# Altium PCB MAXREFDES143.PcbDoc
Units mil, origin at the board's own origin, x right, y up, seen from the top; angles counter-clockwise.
Board outline 3455 x 3500 mil, 2 copper layers (Top Layer, Bottom Layer); 65 components, 50 nets, 221 pads, 48 vias.
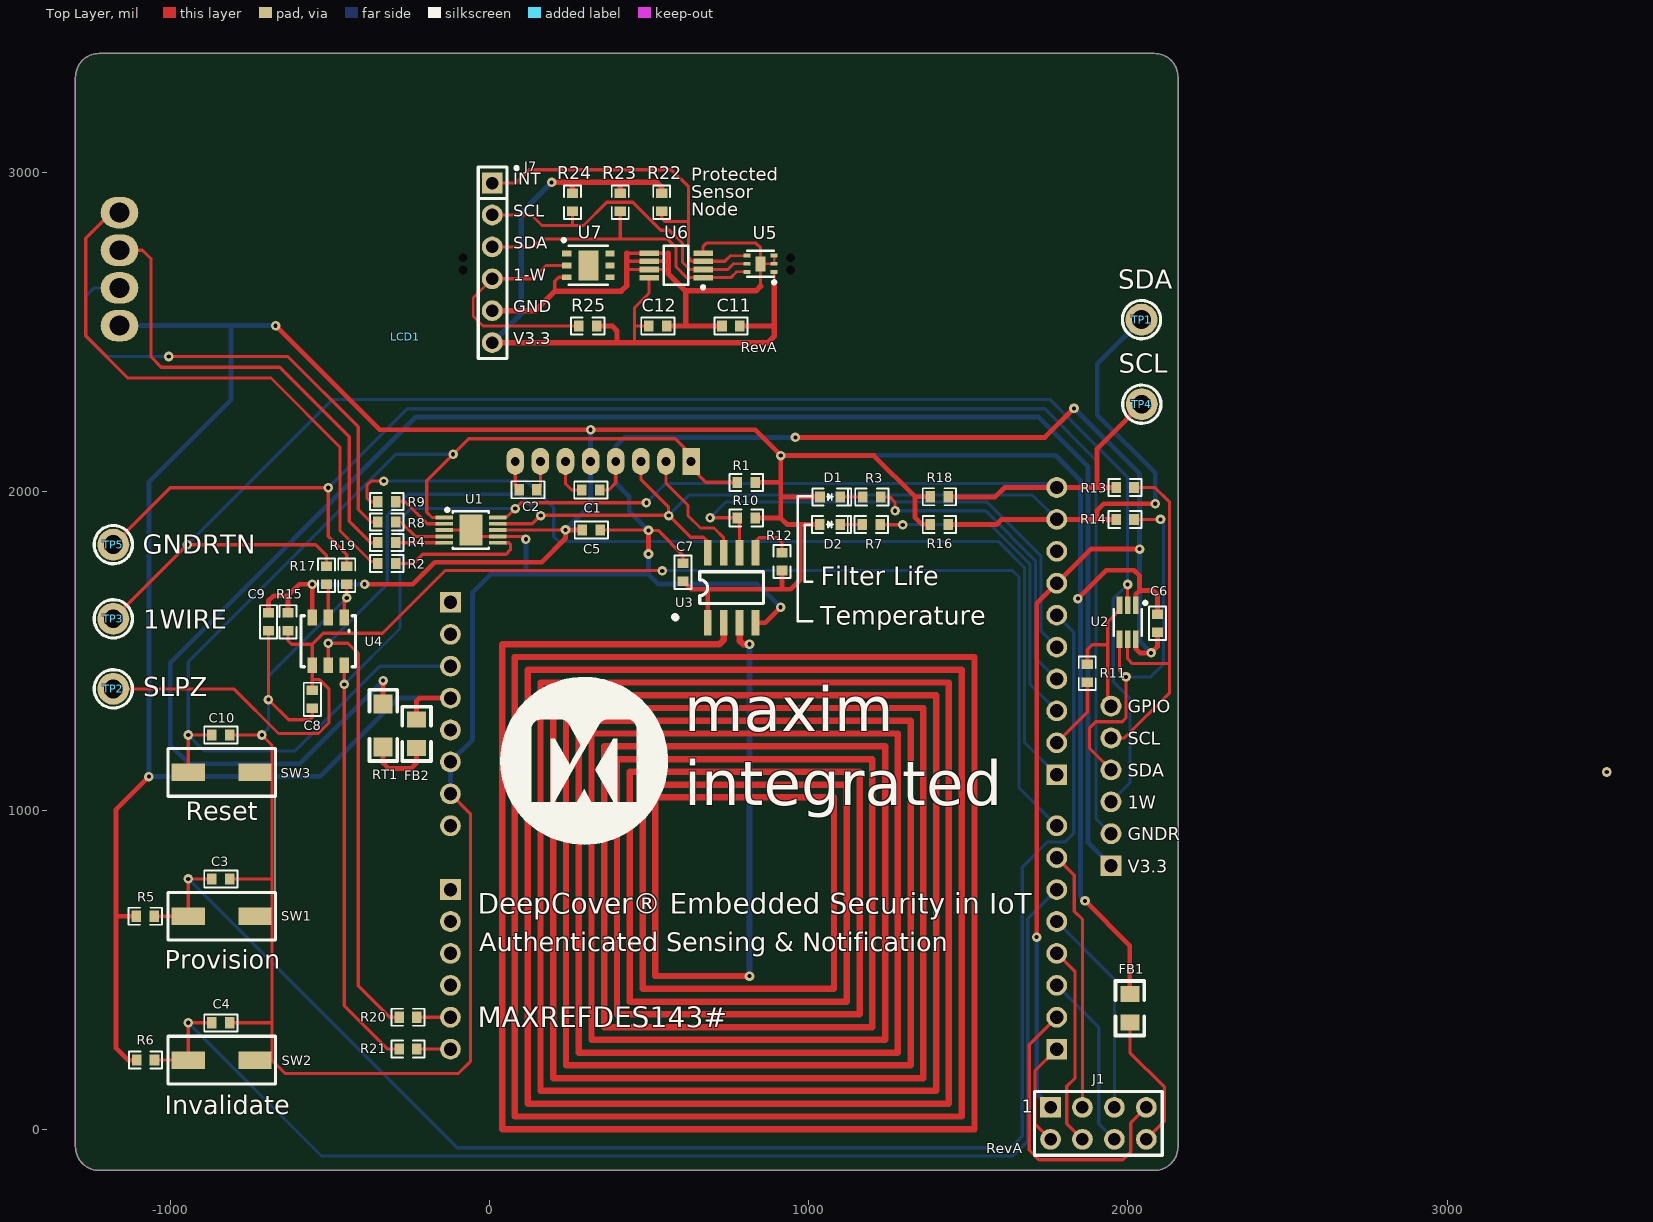
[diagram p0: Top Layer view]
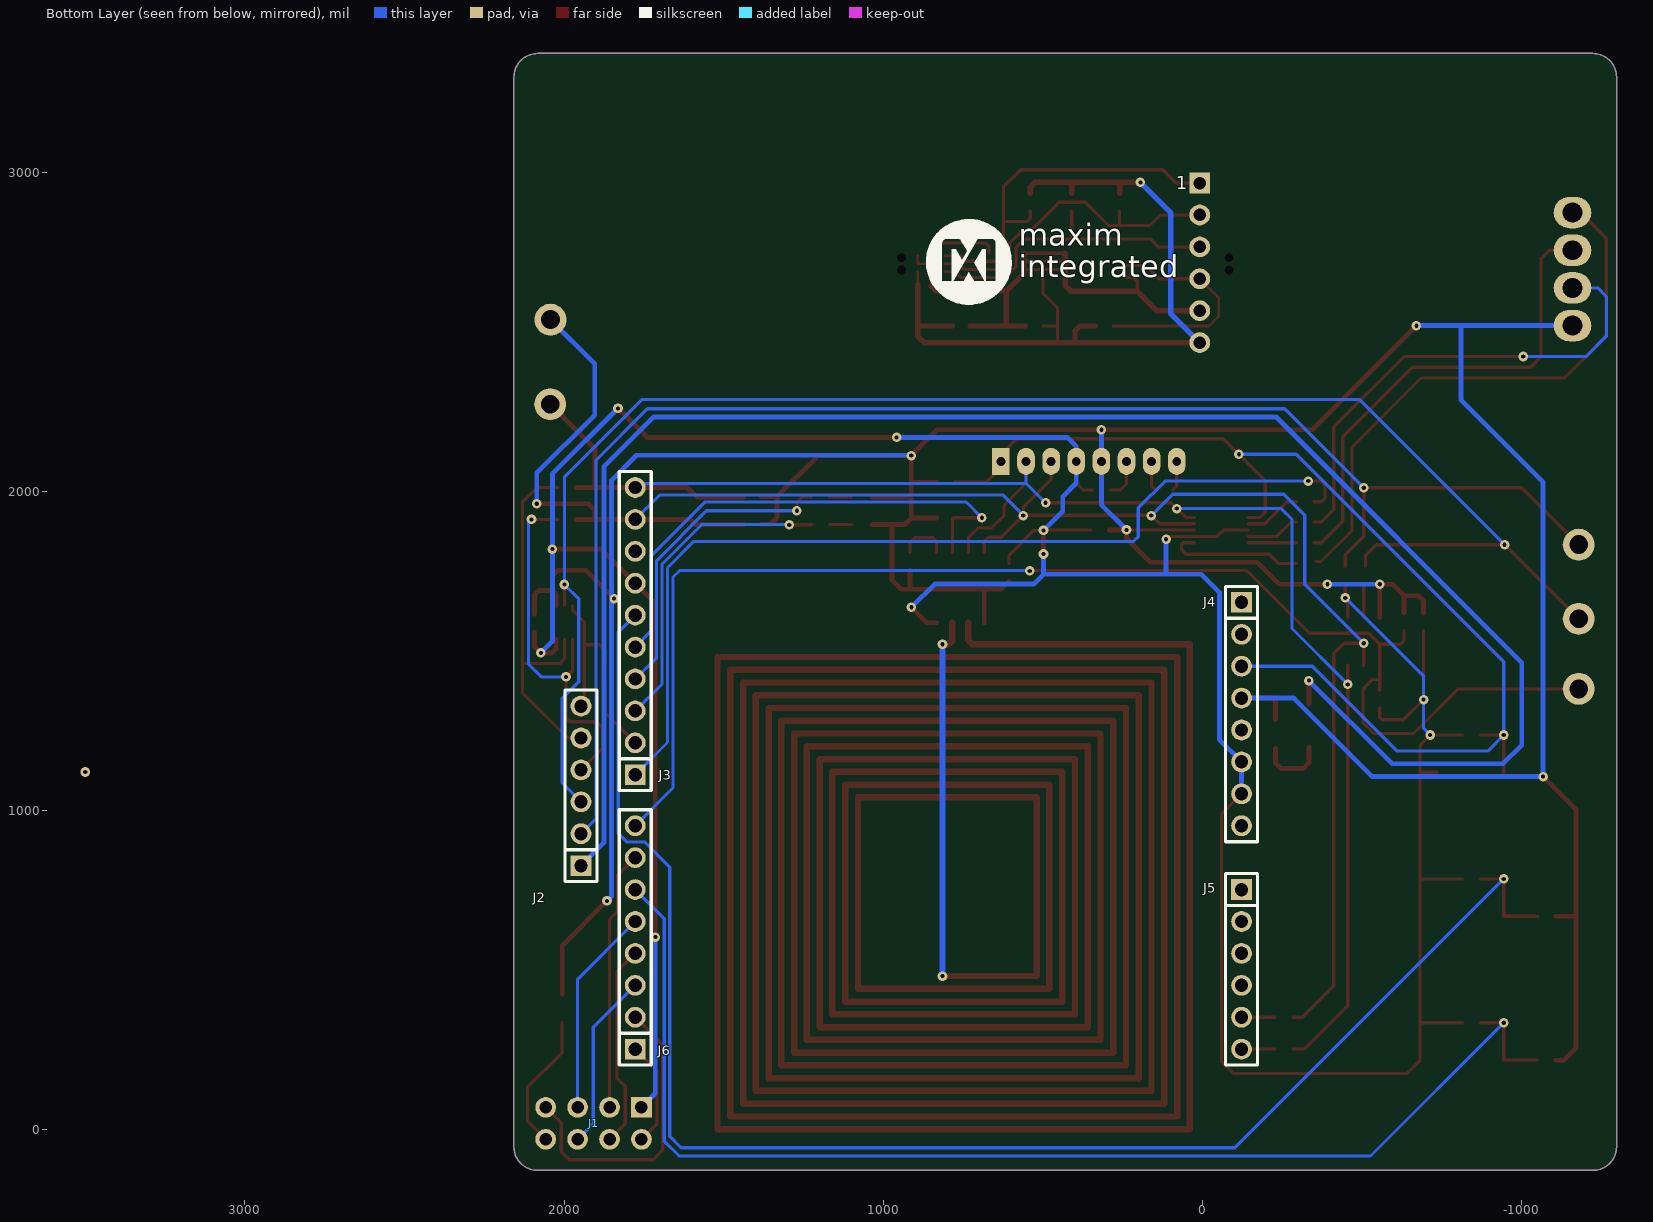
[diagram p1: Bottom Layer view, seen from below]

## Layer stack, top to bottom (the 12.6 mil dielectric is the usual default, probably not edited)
Top Layer: signal copper 1.4
Dielectric: core 12.6, FR-4, Dk 4.8
Bottom Layer: signal copper 1.4

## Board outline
-1298,-53.07 ccw(c-1224.07,-53.07) -1224.07,-127 2083.07,-127 ccw(c2083.07,-53.07) 2157,-53.07 2157,3299.07 ccw(c2083.07,3299.07) 2083.07,3373 -1224.07,3373 ccw(c-1224.07,3299.07) -1298,3299.07

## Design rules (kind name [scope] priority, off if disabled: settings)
Clearance "Clearance GND Layer" [(OnLayer('GND Layer'))] p1: gap=8
Clearance "Clearance V3.3 layer" [(OnLayer('V3.3 Layer'))] p2: gap=8
Clearance [All] p3: gap=7
ComponentClearance [All] p1: gap=0 collisioncheckmode=3 verticalgap=0 showdistances=FALSE
HoleSize [All] p1: absolutevalues=TRUE maxlimit=1000 minlimit=1 maxpercent=80.000 minpercent=20.000
MinimumSolderMaskSliver [All] p1: minsoldermaskwidth=0
PolygonConnect [All] p1: connectstyle=Relief reliefconductorwidth=10 reliefentries=4 polygonreliefangle="90 Angle"
RoomDefinition ProtectedSensorNode [InComponentClass('ProtectedSensorNode')] p1: confinementstyle=ConfineIn formatcopy=TRUE lockcomponents=FALSE outline -348,2304 1114,2304 1114,3140 -348,3140
RoomDefinition mbedShield [InComponentClass('mbedShield')] p2: confinementstyle=ConfineIn formatcopy=TRUE lockcomponents=FALSE outline -1451,-292 2335,-292 2335,3550 -1451,3550
RoutingVias [All] p1: holewidth=6 width=16 viastyle="Through Hole" minholewidth=6 minwidth=12 maxholewidth=17 maxwidth=35
SilkToSilkClearance [All] p1: silktosilkclearance=0
SilkscreenOverComponentPads [All] p1: minsilkscreentomaskgap=4
SolderMaskExpansion [All] p1: expansion=4
Width [All] p1: maxlimit=1111 minlimit=1 preferedwidth=25
23 further rules are at their usual default settings.

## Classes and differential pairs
component class ProtectedSensorNode: C11 C12 J7 R22 R23 R24 R25 U5 U6 U7
component class mbedShield: C1 C2 C3 C4 C5 C6 C7 C8 C9 C10 D1 D2 FB1 FB2 J1 J2 J3 J4 J5 J6 LCD1 R1 R2 R3 R4 R5 R6 R7 R8 R9 R10 R11 R12 R13 R14 R15 R16 R17 R18 R19 R20 R21 RT1 SW1 SW2 SW3 TP1 TP2 TP3 TP4 TP5 U1 U2 U3 U4

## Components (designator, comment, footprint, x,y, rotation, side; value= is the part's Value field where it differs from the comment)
C1 "1uF" CAP0603-3D 289,2005 r0 top
C2 "1uF" CAP0603-3D 148,2006 r180 top
C3 "0.1uF" CAP0603-3D -870.5,786.5 r0 top
C4 "0.1uF" CAP0603-3D -870.5,335.5 r0 top
C5 "0.1uF" CAP0603-3D 290.5,1880 r0 top
C6 "0.1uF" CAP0603-3D 2092.5,1615.5 r270 top
C7 "0.1uF" CAP0603-3D 605.5,1719.5 r90 top
C8 "0.1uF" CAP0603-3D -556,1321 r90 top
C9 "0.1uF" CAP0603-3D -693.5,1564 r90 top
C10 "0.1uF" CAP0603-3D -870.5,1237.5 r0 top
C11 "0.1uF" CAP0603-3D 784,2519 r180 top
C12 "0.1uF" CAP0603-3D 499,2519 r0 top
D1 "RED" 0603LED-3DRED 1099,1983.5 r180 top
D2 "RED" 0603LED-3DRED 1098,1897 r180 top
FB1 "BLM21PG221SN1D" 0805FB-3D 2006,426 r270 top
FB2 "BLM21PG221SN1D" 0805FB-3D -229,1196 r90 top
J1 "ESP8266 Socket" DIH4X2 1757.5,70.5 r270 bottom
J2 "CON6" SIP6 1947,828 r90 bottom locked
J3 "CON10" SIP10-FEM-3D 1777,1113 r90 bottom locked
J4 "CON8" SIP8-FEM-3D -123,1653 r270 bottom locked
J5 "CON6" SIP6-FEM-3D -123,753 r270 bottom locked
J6 "CON8" SIP8-FEM-3D 1777,253 r90 bottom locked
J7 "CON6" SIP6-HEADER-RA-3D 8,2967 r270 top
LCD1 "NHD-C0220BiZ-FS(RGB)-FBW-3VM" "NHD RGB LCD 1" 80,2095 r0 top locked
R1 "DNI" 0603-3D 776,2029 r0 top
R2 "10" 0603-3D -294.63,1775.13 r180 top
R3 "1.5k" 0603-3D 1225.5,1983.5 r180 top
R4 "60.4" 0603-3D -294.63,1840.13 r180 top
R5 "10k" 0603-3D -1051.5,669.5 r180 top
R6 "10k" 0603-3D -1050.5,218.5 r180 top
R7 "1.5k" 0603-3D 1223.5,1897 r180 top
R8 "60.4" 0603-3D -350.63,1904.63 r0 top
R9 "DNI" 0603-3D -294.5,1968.5 r180 top
R10 "10k" 0603-3D 776,1917 r0 top
R11 "10" 0603-3D 1872.5,1403 r90 top
R12 "DNI" 0603-3D 915.5,1809 r270 top
R13 "10" 0603-3D 1963,2013 r0 top
R14 "10" 0603-3D 1963,1913 r0 top
R15 "10K" 0603-3D -632.5,1564 r90 top
R16 "4.7k" 0603-3D 1437,1897.5 r180 top
R17 "5.11" 0603-3D -511,1766 r270 top
R18 "4.7k" 0603-3D 1437,1984 r180 top
R19 "5.11" 0603-3D -448,1766 r270 top
R20 "DNI" 0603-3D -284,353 r0 top
R21 "DNI" 0603-3D -284,253 r0 top
R22 "DNI" 0603-3D 539,2879 r90 top
R23 "DNI" 0603-3D 409,2879 r90 top
R24 "DNI" 0603-3D 259,2879 r90 top
R25 "DNI" 0603-3D 279,2519 r0 top
RT1 "PTC Fuse MF-NSMF012-2" 1206POLYFUSE-3D -334,1200 r90 top
SW1 "PUSH" RESET11-3D -839.81,669.5 r0 top
SW2 "PUSH" RESET11-3D -839.81,218.5 r0 top
SW3 "PUSH" RESET11-3D -839.81,1120.5 r0 top
TP1 "SDA" TP 2042.5,2539 r90 top
TP2 "SLPZ" TP -1179.5,1382 r0 top
TP3 "1-WIRE" TP -1179.5,1601.5 r90 top
TP4 "SCL" TP 2043.5,2274 r90 top
TP5 "GNDRTN" TP -1179.5,1834 r90 top
U1 "MAX7306AUB+" UMAX10 -59,1879.5 r0 top
U2 "MAX13204E" "TDFN6 2MM .65" 2024.5,1643.5 r270 top
U3 "MAX66242" SO-8-3D 683,1589 r90 top
U4 "DS2465" SOP6 -456,1606 r270 top
U5 "MAX44009EDT+" "TDFN6 .65P 2x2MM" 849,2714 r90 top
U6 "DS7505U+" UMAX8 584,2709 r180 top
U7 "DS28E15Q+U" "TDFN6 3MM .95" 309,2709 r0 top

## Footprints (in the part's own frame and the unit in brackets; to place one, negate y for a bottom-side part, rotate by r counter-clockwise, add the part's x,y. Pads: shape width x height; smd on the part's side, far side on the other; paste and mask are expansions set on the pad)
0603-3D [mil]
  rect 30x35 smd: 1(0,0) 2(56,0)
  silkscreen extent -24,-27 80,27, body extent -3,-17 59,17, height 18
0603LED-3DRED [mil]
  rect 30x35 smd: 1(0,0) 2(64,0)
  silkscreen extent -34,-27 88,27, body extent 0,-16 64,15, height 24
0805FB-3D [mil]
  rect 50x60 smd: 1(0,0) 2(90,0)
  silkscreen extent -40,-45 130,45, body extent 6,-24 84,25, height 47
1206POLYFUSE-3D [mil]
  rect 60x60 smd: 1(0,0) 2(134,0)
  silkscreen extent -44,-44 179,43, body extent 4,-33 130,33, height 22
CAP0603-3D [mil]
  rect 30x35 smd: 1(0,0) 2(56,0)
  silkscreen extent -24,-27 80,27, body extent -3,-16 59,16, height 31
DIH4X2 [mil] "dual inline header 4x2 pins"
  rect 65x65 hole 39: 1(0,0)
  round 65 hole 39: 2(100,0) 3(0,-100) 4(100,-100) 5(0,-200) 6(100,-200) 7(0,-300) 8(100,-300)
"NHD RGB LCD 1" [mil] "NHD-C0220BiZ-FSRGB-FBW-3VM"
  rect 55x85 hole 28: 1(551.18,0)
  oval 55x85 hole 28: 2(472.44,0) 3(393.7,0) 4(314.96,0) 5(236.22,0) 6(157.48,0) 7(78.74,0) 8(0,0)
  oval 118.11x98.43 hole 62: A(-1240.16,425.2) B(-1240.16,543.31) G(-1240.16,661.42) R(-1240.16,779.53)
  body extent -1296,-210 1685,1277, height 60
RESET11-3D [mm]
  rect 2.65x1.4 smd: 1(-2.663,0) 2(2.658,0)
  silkscreen extent -4.28,-1.9 4.28,1.9, body extent -3.56,-1.78 3.55,1.78, height 2.54
SIP6 [mil]
  rect 65x65 hole 42: 1(0,0)
  round 65 hole 42: 2(100,0) 3(200,0) 4(300,0) 5(400,0) 6(500,0)
  silkscreen extent -50,-50 550,50
SIP6-FEM-3D [mil]
  rect 65x65 hole 42: 1(0,0)
  round 65 hole 42: 2(100,0) 3(200,0) 4(300,0) 5(400,0) 6(500,0)
  silkscreen extent -50,-50 550,50, body extent -48,-56 549,56, height 336
SIP6-HEADER-RA-3D [mil]
  rect 65x65 hole 39: 1(0,0)
  round 65 hole 39: 2(100,0) 3(200,0) 4(300,0) 5(400,0) 6(500,0)
  silkscreen extent -52,-44 550,81, body extent -50,-354 550,13, height 140
SIP8-FEM-3D [mil]
  rect 65x65 hole 42: 1(0,0)
  round 65 hole 42: 2(100,0) 3(200,0) 4(300,0) 5(400,0) 6(500,0) 7(600,0) 8(700,0)
  silkscreen extent -50,-50 750,50, body extent -48,-56 749,56, height 336
SIP10-FEM-3D [mil]
  rect 65x65 hole 42: 1(0,0)
  round 65 hole 42: 2(100,0) 3(200,0) 4(300,0) 5(400,0) 6(500,0) 7(600,0) 8(700,0) 9(800,0) 10(900,0)
  silkscreen extent -50,-50 950,50, body extent -48,-56 949,56, height 336
SO-8-3D [mil]
  rect 80x24 smd: 1(0,0) 2(0,-50) 3(0,-100) 4(0,-150) 5(220,-150) 6(220,-100) 7(220,-50) 8(220,0)
  silkscreen extent 60,-175 160,25, body extent -8,-172 228,20, height 69
SOP6 [mil]
  rect 50x30 smd: 1(0,0) 2(0,-50) 3(0,-100) 4(150,-100) 5(150,-50) 6(150,0)
  silkscreen extent -5,-135 155,35
"TDFN6 2MM .65" [mm]
  rect 1.4x0.45 smd mask+0.127: 1(0,0) 2(0,-0.65) 3(0,-1.3) 4(2.7,-1.3) 5(2.7,-0.65) 6(2.7,0)
  silkscreen extent -0.33,-1.77 2.4,0.88, body extent 0.33,-1.67 2.37,0.38, height 0.8
"TDFN6 3MM .95" [mm]
  rect 0.75x0.46 smd: 1(-1.725,0.95) 2(-1.725,0) 3(-1.725,-0.95) 4(1.725,-0.95) 5(1.725,0) 6(1.725,0.95)
  rect 1.6x2.39 smd: EP(0,0)
  silkscreen extent -2.08,-1.55 1.55,2.13, body extent -1.55,-1.55 1.55,1.55, height 0.75
"TDFN6 .65P 2x2MM" [mm]
  rect 0.3x0.55 smd: 1(-0.65,-1.075) 2(0,-1.075) 3(0.65,-1.075) 4(0.65,1.075) 5(0,1.075) 6(-0.65,1.075)
  rect 1.2x0.8 smd: EP(0,0)
  silkscreen extent -1.6,-1.2 1.05,1.05, body extent -1.04,-1.04 1.04,1.04, height 0.65
TP [mil]
  round 100 hole 59: 1(0,0)
  silkscreen extent -60,-60 60,60
UMAX8 [mm]
  rect 1.55x0.45 smd: 1(-2.15,0.975) 2(-2.15,0.325) 3(-2.15,-0.325) 4(-2.15,-0.975) 5(2.15,-0.975) 6(2.15,-0.325) 7(2.15,0.325) 8(2.15,0.975)
  silkscreen extent -2.28,-1.55 0.97,1.87, body extent -2.44,-1.51 2.46,1.49, height 1.15
UMAX10 [mm] "TSSOP, 10-Leads, Body 3.0x3.0mm (max), Pitch 0.50mm, IPC Medium Density"
  rect 1.4x0.3 smd: 1(-2.135,1) 2(-2.135,0.5) 3(-2.135,0) 4(-2.135,-0.5) 5(-2.135,-1) 6(2.135,-1) 7(2.135,-0.5) 8(2.135,0) 9(2.135,0.5) 10(2.135,1)
  rect 1.85x2.47 smd: EP(0,0)
  silkscreen extent -2,-1.5 1.42,1.74, body extent -1.5,-1.5 1.5,1.5, height 1.1

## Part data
C1 C2: library part CAP, "CAP CER 1UF 10V 10% X7R 0603"
C3 C4 C5 C6 C7 C8 C9 C10 C11 C12: library part CAP, "CAP CER 0.1UF 16V 10% X7R 0603"
D1 D2: library part LED, "LED RED RECT CLEAR 0603"
FB1 FB2: library part FUSE1, "Ferrite Chip"
J1: library part "JUMPBLOCK 4", "8 Position Header Socket 0.100\" (2.54mm) Through Hole"
J2: "6 Position Header Socket 0.100\" (2.54mm) Through Hole, Right Angle"
J3: "10 Position Header 0.100\" (2.54mm) Through Hole"
J4 J6: "8 Position Header 0.100\" (2.54mm) Through Hole"
J5: "6 Position Header 0.100\" (2.54mm) Through Hole"
J7: "6 Position Header 0.100\" (2.54mm) Through Hole, Right Angle"
LCD1: library part "NHD C0220BiZ-FS(RGB)-FBW-3VM", "LCD DISPLAY RGB LED BKLT 20 X 2"
R1: library part RESISTOR, "RES 10K OHM 1/10W 1% 0603 SMD"
R2 R11 R13 R14: library part RESISTOR, "RES 10 OHM 1/10W 1% 0603 SMD"
R3 R7: library part RESISTOR, "RES SMD 1.5K OHM 1% 1/10W 0603"
R4 R9 R12 R20 R21 R22 R23 R24 R25: library part RESISTOR
R5 R6 R10 R15: library part RESISTOR, "RES SMD 10K OHM 1% 1/10W 0603"
R8: library part RESISTOR, "RES 60.4 OHM 1/10W 1% 0603 SMD"
R16 R18: library part RESISTOR, "RES SMD 4.7K OHM 1% 1/10W 0603"
R17 R19: library part RESISTOR, "RES SMD 5.11 OHM 1% 1/10W 0603"
RT1: library part THERMISTOR, "PTC Fuse 1206"
SW1 SW2 SW3: library part SW-PB, "SWITCH TACTILE SPST-NO 0.05A 32V"
TP1 TP2 TP3 TP4 TP5: library part TP, "Test Point"
U1: library part MAX7306, "SMBus/I²C Interfaced 4-Port, Level-Translating GPIOs and LED Drivers"
U2: library part MAX13204, "4 Channel +/- 30kv ESD Protector"
U3: library part MAX2XXX, "DeepCover Secure Authenticator with ISO 15693, I²C, SHA-256, and 4Kb User EEPROM"
U4: library part DSKCP1, "DeepCover Secure Authenticator with SHA-256 Coprocessor and 1-Wire Master Function"
U5: library part MAX44009, "Ambient Light Sensor with ADC"
U6: library part DS75, "Digital Thermometer and Thermostat"
U7: library part "DS28E15 TDFN", "DeepCover Secure Authenticator with 1-Wire SHA-256 and 512-Bit User EEPROM"

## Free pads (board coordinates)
  round 0 hole 28 unplated: ""(-84,2694) ""(-84,2733) ""(943,2694) ""(943,2733) ""(3498.5,961)
  round 0 hole 28: ""(3497,801)
  round 0 hole 59: ""(3497.5,488)
  round 0 hole 39: ""(3498,648)
  round 0 hole 62: ""(3500,333)

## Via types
v1: diameter 30, hole 13, Top Layer to Bottom Layer, tented both sides, 48 vias

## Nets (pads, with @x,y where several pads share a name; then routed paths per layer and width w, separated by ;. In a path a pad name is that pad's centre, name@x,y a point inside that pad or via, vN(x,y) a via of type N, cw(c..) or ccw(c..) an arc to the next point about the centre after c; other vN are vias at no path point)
1-WIRE: J2.3 R17.1 TP3.1 U2.2 | length 5195.1
  Top Layer w10: TP3.1 v1(-947.38,1833.62) -545.62,1833.62 -511,1799 R17.1 ; U2.2 v1(1998.91,1709)
  Bottom Layer w10: v1(-947.38,1833.62) -492,2289 1755,2289 1998.91,2045.09 v1(1998.91,1709) 1954,1664.09 1954,1404 2006,1352 2006,1087 J2.3
1-WIRE_PSN: J7.4 R25.1 U7.2 | length 735.3
  Top Layer w8: J7.4 -51,2608 -51,2549 -21,2519 R25.1
  Top Layer w10: J7.4 136,2667 178,2709 U7.2
BLUE: R8.2 U1.4 | length 170.1
  Top Layer w10: R8.2 -278.13,1904.63 -233.32,1859.82 U1.4
GND: C1.2 C3.2 C4.2 C5.2 C6.2 C7.2 C8.1 C9.1 C10.2 J1.1 J3.7 J4.6 J4.7 LCD1.4 R19.2 SW1.2 SW2.2 SW3.2 U1.3 U1.7 U1.EP U2.6 U3.4 U4.1 | length 11578.2
  Top Layer w10: C4.2 -682.5,335.5 ; C3.2 -682.5,786.5 ; C10.2 v1(-714,1237.5) -682.5,1206 -682.5,1120.5 ; SW3.2 -682.5,1120.5 ; C9.1 v1(-693.5,1348.5) -630,1285 -564,1285 -556,1293 C8.1 ; U4.1 -456,1659 v1(-448,1667) R19.2 ; U1.3 -67,1879.5 -47.32,1859.81 104.68,1859.81 v1(113.5,1851) ; J4.7 -60.5,990.5 -60.5,214 -98,176.5 -640.5,176.5 -682.5,218.5 -682.5,335.5 ; C1.2 372.5,2005 394.96,2027.46 LCD1.4 ; C5.2@348.46,1880 v1@497.5,1880 ; v1(497.5,1878.5) 528,1878.5 605.5,1801 C7.2 ; -682.5,335.5 -682.5,786.5 ; -682.5,786.5 -682.5,1120.5
  Top Layer w15: v1(497.5,1804.5) v1(497.5,1878.5) ; U3.4 863,1589 v1(911.5,1637.5) ; v1(958,2170) 1740,2170 v1(1831,2261) ; v1(1714,604) 1714,1650 J3.7 1884,1820 v1(2036.5,1820) ; U2.6 2024.5,1507 2037,1494.5 v1(2072.5,1494.5) 2092.5,1514.5 C6.2
  Bottom Layer w10: v1(-714,1237.5) -693.5,1258 v1(-693.5,1348.5) -693.5,1421.5 v1(-448,1667)
  Bottom Layer w15: J4.7 J4.6 -53.5,1222.5 -53.5,1684 3.5,1741 114,1741 ; v1@114,1850.5 114,1741 ; v1(497.5,1804.5) 497.5,1741 ; v1(497.5,1878.5) 437.5,1938.5 437.5,1984.5 394.96,2027.04 LCD1.4 394.96,2141.96 423,2170 v1(958,2170) ; v1(911.5,1637.5) 838.5,1710.5 528,1710.5 497.5,1741 ; v1(1714,604) 1714,114 J1.1 ; v1(1831,2261) 2036.5,2055.5 v1(2036.5,1820) 2036.5,1530.5 v1(2072.5,1494.5) ; 114,1741 497.5,1741
GND_PSN: C11.2 C12.2 J7.5 U5.2 U5.3 U5.EP U6.4 U6.5 U6.6 U6.7 U7.3 | length 2081.6
  Top Layer w8: U5.EP@854,2714 U5.2 U5.3
  Top Layer w10: 204,2628.01 204,2659 216.6,2671.6 U7.3 ; 429,2696.2 U6.7 559,2696.2 ; 429,2721.8 U6.6 559,2721.8 ; 429,2746.8 559,2746.8 ; U6.4 668.65,2768.65 679,2779 834,2779 849,2764 849,2719 U5.EP 849,2644
  Top Layer w17: J7.5 142.99,2567 204,2628.01 412.01,2628.01 429,2645 429,2696.2 429,2721.8 429,2746.8 ; C12.2 614,2519 ; 559,2746.8 559,2721.8 559,2696.2 559,2684 614,2629 ; C11.2 614,2519 ; 849,2644 834,2629 614,2629 ; U5.EP@849,2719 U5.EP@851.41,2716.59 ; 614,2519 614,2629
GND_RTN: J2.2 R19.1 TP5.1 | length 4783.1
  Top Layer w10: TP5.1 -1001.5,2012 v1(-506,2012) -506,1860 -448,1802 R19.1
  Bottom Layer w10: v1(-506,2012) -258,2260 1739,2260 1900,2099 1900,975 J2.2
GPIO: J2.6 R11.2 U2.3 | length 450.7
  Top Layer w10: R11.2 1872.5,1504 1888.5,1520 1936.5,1520 ; J2.6 1936.5,1338.5 1936.5,1520 ; U2.3 1973.32,1628.32 1936.5,1591.5 1936.5,1520
GREEN: R4.1 U1.5 | length 151.6
  Top Layer w10: R4.1 U1.5
I\N\T\_PSN: J7.1 R22.1 U5.4 U6.3 | length 1183.1
  Top Layer w8: 754.59,2739.59 U5.4
  Top Layer w10: J7.1 82,2967 124,3009 569,3009 623.13,2954.87 623.13,2847 ; R22.1 539,2857 549,2847 623.13,2847 ; 754.59,2739.59 736.8,2721.8 U6.3 633.65,2721.8 623.13,2732.31 623.13,2847
IO: R17.2 U4.2 | length 106.1
  Top Layer w10: R17.2 -506,1705 U4.2
NetC1_1: C1.1 LCD1.6 | length 130.1
  Top Layer w10: LCD1.6 237.48,2024.52 257,2005 C1.1
NetC2_1: C2.1 LCD1.7 | length 93.4
  Top Layer w10: C2.1 158.74,2016.74 LCD1.7
NetC2_2: C2.2 LCD1.8 | length 94
  Top Layer w10: LCD1.8 80,2018 C2.2
NetD1_1: D1.1 R3.2 | length 70.5
  Top Layer w10: D1.1 R3.2
NetD2_1: D2.1 R7.2 | length 69.5
  Top Layer w10: D2.1 R7.2
NetFB1_2: FB1.2 J1.8 | length 434.5
  Top Layer w10: FB1.2 2006,242 2115,133 2115,28 J1.8
NetFB2_1: FB2.1 RT1.1 | length 215.9
  Top Layer w15: RT1.1 -334,1150 -316,1132 -247,1132 -229,1150 FB2.1
NetJ5_5: J5.5 R20.2 | length 105
  Top Layer w10: R20.2 J5.5
NetJ5_6: J5.6 R21.2 | length 105
  Top Layer w10: R21.2 J5.6
NetLCD1_B: LCD1.B R8.1 | length 1550.5
  Top Layer w10: v1(-1006,2423.5) -632.5,2423.5 -412,2203 -412,1944 -373,1905 R8.1@-351,1905
  Bottom Layer w10: LCD1.B -1239.69,2638.31 -1266.5,2611.5 -1266.5,2486.5 -1203.5,2423.5 v1(-1006,2423.5)
NetLCD1_G: LCD1.G R4.2 | length 1524.1
  Top Layer w10: LCD1.G -1087.92,2756.42 -1061.5,2730 -1061.5,2422.5 -1029,2390 -658.5,2390 -440,2171.5 -440,1907 -373.13,1840.13 R4.2
NetLCD1_R: LCD1.R R2.2 | length 1801
  Top Layer w10: LCD1.R -1185.97,2874.53 -1266,2794.5 -1266,2488 -1134,2356 -685.5,2356 -469,2139.5 -469,1878 -372,1781 R2.2@-356.5,1781
NetR9_1: R9.1 U1.2 | length 180.2
  Top Layer w10: R9.1 -265.5,1968.5 -196.19,1899.19 U1.2
NetR12_1: R12.1 U3.5 | length 160.9
  Top Layer w10: U3.5 833,1844.5 844,1855.5 901.5,1855.5 915.5,1841.5 R12.1
NetU3_2: U3.2 U3.3 | length 52659.9
  Top Layer w20: U3.2 733,1535 720,1522 39,1522 39,2 1519,2 1519,1482 79,1482 79,42 1479,42 1479,1442 119,1442 119,82 1439,82 1439,1402 159,1402 159,122 1399,122 1399,1362 199,1362 199,162 1359,162 1359,1322 239,1322 239,202 1319,202 1319,1282 279,1282 279,242 1279,242 1279,1242 319,1242 319,282 1239,282 1239,1202 359,1202 359,322 1199,322 1199,1162 399,1162 399,362 1159,362 1159,1122 439,1122 439,402 1119,402 1119,1082 479,1082 479,442 1079,442 1079,1042 519,1042 519,482 v1(814,482) ; U3.3 783,1533 794,1522 v1(814,1522)
  Bottom Layer w20: v1(814,482) v1(814,1522)
P10_TX: J1.2 J6.1 | length 331.2
  Top Layer w10: J1.2 1708.5,19.5 1708.5,184.5 J6.1
P11_RX: J1.7 J6.2 | length 952.4
  Top Layer w10: J6.2 1690.5,266.5 1690.5,-63 1721,-93.5 1984,-93.5 2009,-68.5 2009,22 J1.7
P12_RST: J1.6 J6.3 | length 557.3
  Bottom Layer w10: J6.3 1908.5,321.5 1908.5,19.5 J1.6
P13_CH_PD: J1.4 J6.4 | length 637.4
  Top Layer w10: J6.4 1834.5,495.5 1834.5,162.5 1808.5,136.5 1808.5,19.5 J1.4
P14_GPIO0: J1.5 J6.5 | length 657.3
  Bottom Layer w10: J6.5 1957.5,472.5 J1.5
P15_PUSH: C4.1 J6.6 R6.1 SW2.1 | length 3946
  Top Layer w10: R6.1 SW2.1 v1(-944.63,335.5) C4.1
  Bottom Layer w10: v1(-944.63,335.5) -527.13,-82 1639.5,-82 1686,-35.5 1686,662 J6.6
P16_GPIO2: J1.3 J6.7 | length 815.8
  Top Layer w10: J6.7 1832,798 1832,685 1857.5,659.5 J1.3
P17_SLPZ: C8.2 J6.8 R15.1 TP2.1 U4.4 | length 4322.2
  Top Layer w10: TP2.1 -802,1382 -662,1242 -537,1242 -504,1275 -504,1382 -533,1411 -556,1411 ; R15.1 -632.5,1533.5 -621,1522 -556,1522 ; C8.2 -556,1411 ; v1@540.5,1753 -139,1753 -336,1556 -522,1556 -556,1522 ; -556,1411 U4.4 -556,1522
  Bottom Layer w10: v1@540.5,1753 1638,1753 1658.5,1732.5 1658.5,1071.5 J6.8
  other v1: 540.5,1751.5
P20_PUSH: C3.1 J3.6 R5.1 SW1.1 | length 5030
  Top Layer w10: R5.1 SW1.1 v1(-944.63,786.5) C3.1
  Bottom Layer w10: v1(-944.63,786.5) -102.13,-56 1633.5,-56 1669,-20.5 1669,823.5 1748,902.5 1803.5,902.5 1830,929 1830,1560 J3.6
P21_LED: J3.4 R3.1 | length 982.6
  Top Layer w10: R3.1 1253,1983.5 1270.5,1966 v1(1270.5,1940)
  Bottom Layer w10: v1@1269,1940 v1(1270.5,1940) 1554,1940 1710,1784 1710,1480 J3.4
P22_INT_NFC: J3.5 R10.1 U3.6 | length 1626.9
  Top Layer w10: v1(690.5,1918) R10.1@776,1918 ; U3.6 R10.1@783,1916.5
  Bottom Layer w10: v1(690.5,1918) 740.5,1968 1558,1968 1728,1798 1728,1562 J3.5
P23_LED: J3.3 R7.1 | length 1016.6
  Top Layer w10: R7.1 1224.5,1896 v1(1294.5,1896)
  Bottom Layer w10: v1@1294,1897 1569,1897 1693,1773 1693,1397 J3.3
P24_GPIO: J3.2 R11.1 | length 229.6
  Top Layer w10: J3.2 1872.5,1308.5 R11.1
P25_INT_LCD: J3.1 R9.2 | length 3000.9
  Top Layer w10: R9.2 -373.5,1968.5 -385,1980 -385,2020 -372,2033 v1(-332,2033)
  Bottom Layer w10: v1(-332,2033) 116.5,2033 200.5,1949 200.5,1859 215.5,1844 1593,1844 1676,1761 1676,1214 J3.1
P26_SDA: J3.9 LCD1.3 R14.1 R16.1 R20.1 TP1.1 U1.9 U3.8 U4.5 | length 6078.3
  Top Layer w10: U4.5 v1(-506,1525) -444,1525 -412,1493 -412,451.5 -313.5,353 R20.1 ; U1.9 132.82,1899.19 159.63,1926 v1@560.5,1926 ; LCD1.3 473.7,2038.3 560.5,1951.5 v1@560.5,1926 ; U3.8 683,1844 670,1857 629.5,1857 v1@560.5,1926
  Top Layer w15: R16.1@1437,1897 1589,1897 1605,1913 J3.9 1903.5,1913 ; R14.1 1903.5,1913 ; v1(2085.5,1962) 1924.5,1962 1903.5,1941 1903.5,1913
  Bottom Layer w10: v1(-506,1525) -321,1710 -321,1926 -255,1992 93.13,1992 v1(160.13,1925) ; v1@560.5,1926 623.5,1989 1701,1989 J3.9
  Bottom Layer w15: TP1.1 1904,2400.5 1904,2240 2085.5,2058.5 v1(2085.5,1962)
  other v1: 561,1925
P27_SCL: J3.10 LCD1.2 R13.1 R18.1 R21.1 TP4.1 U1.10 U3.7 U4.6 | length 5373.4
  Top Layer w10: U4.6 v1(-456,1396) -456,389.5 -319.5,253 R21.1 ; U1.10 51.87,1918.87 v1(80,1947) 98,1965 v1(491,1965) ; LCD1.2 552.44,2026.06 621.5,1957 621.5,1925 660.5,1886 703,1886 733,1856 U3.7
  Top Layer w15: R18.1@1437,1983.5 1584.5,1983.5 1614,2013 J3.10 1903.5,2013 ; R13.1 1903.5,2013 ; TP4.1 1903.5,2134 1903.5,2013
  Bottom Layer w10: v1(-456,1396) -281,1571 -281,1913 -247,1947 v1(80,1947) ; v1@491,1964.5 552.44,2025.94 ; LCD1.2 552.44,2025.94 ; J3.10 1764.06,2025.94 552.44,2025.94
RED: R2.1 U1.6 | length 437
  Top Layer w10: R2.1 -238.37,1775.13 -209.5,1804 51.5,1804 65,1817.5 65,1835.5 60.37,1840.13 U1.6
RSTN: C10.1 J4.3 LCD1.1 R1.1 SW3.1 U1.1 | length 3741.2
  Top Layer w10: SW3.1 v1(-944.63,1237.5) C10.1 ; U1.1 -180.87,1918.87 -197.5,1935.5 -197.5,2034.5 -66,2166 581,2166 631.18,2115.82 LCD1.1 631.18,2074.82 676.5,2029.5 R1.1@776,2029.5
  Bottom Layer w10: J4.3 -345,1453 -611,1187 -894.13,1187 v1(-944.63,1237.5) -944.63,1466.37 -294,2117 v1(-114.5,2117)
SCL: J2.5 R13.2 U2.5 | length 1168.8
  Top Layer w10: J2.5 1989,1228 2130.5,1369.5 2130.5,1461 ; U2.5 1998.91,1476.09 2014,1461 2130.5,1461 ; R13.2 2084,2013 2130.5,1966.5 2130.5,1461
SCL_PSN: J7.2 R24.1 U5.5 U6.2 | length 1016.8
  Top Layer w8: 764,2714 U5.5
  Top Layer w10: J7.2 131,2867 164,2834 259,2834 ; R24.1 259,2834 ; 764,2714 746.2,2696.2 U6.2 626.8,2696.2 604,2719 604,2778 563,2819 536,2819 448,2907 367,2907 294,2834 259,2834
SDA: J2.4 R14.2 U2.4 | length 1215.9
  Top Layer w10: J2.4 1880,1195 1880,1260 1899,1279 1982,1279 1994,1291 v1(1994,1419.5) 1973.32,1440.18 U2.4 ; R14.2 v1(2102,1913)
  Bottom Layer w10: v1(1994,1419.5) 2071.5,1419.5 2111.5,1459.5 2111.5,1903.5 v1(2102,1913)
SDA_PSN: J7.3 R23.1 U5.6 U6.1 | length 988.8
  Top Layer w8: 773.41,2688.41 U5.6
  Top Layer w10: J7.3 138,2767 163,2792 409,2792 ; R23.1 409,2792 ; 773.41,2688.41 755.61,2670.61 U6.1 617.39,2670.61 584,2704 584,2764 556,2792 409,2792
V3.3: C5.1 C6.1 C7.1 C9.2 D1.2 D2.2 FB1.1 FB2.2 J4.4 LCD1.5 LCD1.A R1.2 R5.2 R6.2 R10.2 R12.2 R15.2 R16.2 R18.2 U1.8 U2.1 U3.1 U4.3 | length 12950.8
  Top Layer w10: U1.8 v1@237.5,1879.5
  Top Layer w15: R5.2 -1171.5,669.5 ; R6.2 -1133,218.5 -1171.5,257 -1171.5,669.5 ; v1(-1068,1107) -1171.5,1003.5 -1171.5,669.5 ; C9.2@-693.5,1619.5 -693.5,1657.5 -677,1674 -632.5,1674 ; v1(-671,2520) -345,2194 v1(316.22,2194) 831.5,2194 912,2113.5 v1(912,2113) ; R15.2 -632.5,1674 ; U4.3 v1(-556,1710) -596.5,1710 -632.5,1674 ; v1(-392,1710) -241,1710 -172,1779 162.5,1779 237.5,1854 237.5,1879.5 v1(237.5,1880) C5.1 ; FB2.2 -229,1344 -220,1353 J4.4 ; C7.1 631,1694 683,1694 ; U3.1 683,1694 ; R10.2 912,1917 ; R1.2@832,2029.5 912,2029.5 ; R12.2 915.5,1694 ; 972,1895.5 972,1722.5 943.5,1694 915.5,1694 ; D2.2 932,1897 912,1917 ; D1.2 912,1983.5 ; R16.2 1353.5,1897.5 1333,1918 1333,1984 ; R18.2 1333,1984 ; v1(1843,1665) 1931.5,1753.5 2019,1753.5 2036.5,1736 2036.5,1690 ; v1(1865.5,717.5) 2006,577 FB1.1 ; U2.1 2024.5,1678 2036.5,1690 ; C6.1 2092.5,1678 2080.5,1690 2036.5,1690 ; 683,1694 915.5,1694 ; 912,1917 912,1983.5 ; 912,1983.5 912,2029.5 ; 912,2029.5 v1(912,2113) ; v1(912,2113) 1204,2113 1333,1984
  Bottom Layer w15: LCD1.A -810.5,2520.2 ; v1@-671,2520.2 -810.5,2520.2 ; v1(-556,1710) v1(-392,1710) ; J4.4 -287,1353 -533,1107 v1(-1068,1107) -1068,2030 -810.5,2287.5 -810.5,2520.2 ; v1(237.5,1880) 316.22,1958.72 LCD1.5 v1(316.22,2194) ; v1@911.5,2114 1773,2114 1851,2036 1851,1673 v1(1843,1665) 1851,1657 1851,732 v1(1865.5,717.5)
VCC3.3X: J2.1 RT1.2 | length 5670.9
  Top Layer w15: RT1.2 v1(-334,1408)
  Bottom Layer w15: v1(-334,1408) -595,1147 -942,1147 -1001,1206 -1001,1464 -231,2234 1719,2234 1875,2078 1875,900 J2.1
VCC_PSN: C11.1 C12.1 J7.6 R22.2 R23.2 R24.2 R25.2 U5.1 U6.8 | length 2592.6
  Top Layer w8: 891.32,2649 U5.1
  Top Layer w10: 454,2467 454,2519 ; C12.1 454,2519 ; U6.8 499.35,2622.35 454,2577 454,2519
  Top Layer w17: J7.6 399,2467 ; v1(194,2969) 259,2969 ; R24.2 259,2969 ; R25.2 384,2519 399,2504 399,2467 ; R23.2 409,2969 ; R22.2 539,2954 524,2969 409,2969 ; C11.1 891.32,2519 ; 891.32,2649 891.32,2519 ; 259,2969 409,2969 ; 399,2467 454,2467 872,2467 891.32,2486.32 891.32,2519
  Bottom Layer w17: J7.6 99.22,2558.22 99.22,2874.22 v1(194,2969)
pads on no net: J3.8 J4.1 J4.2 J4.5 J4.8 J5.1 J5.2 J5.3 J5.4 U7.1 U7.4 U7.5 U7.6 U7.EP
copper on no net:
  other v1: 3500.5,1121.5

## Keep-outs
Keep-Out Layer:
  the board outline again, w1

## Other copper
Top Layer:
  text "Top Layer" at 2742,-503 h53
Bottom Layer:
  text "Bottom Layer" at 2742.5,-698.5 h53
  text "Bottom Layer" at 5115.14,-705.69 h53

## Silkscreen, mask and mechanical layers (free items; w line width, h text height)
Top Overlay:
  drawing of 9 lines, arcs and shapes, not listed
  text "Protected" at 632,2960 h70
  text "INT" at 74,2949 h65
  text "Sensor" at 632,2905 h70
  text "Node" at 632,2850 h70
  text "SCL" at 74,2849 h65
  text "SDA" at 74,2749 h65
  text "1-W" at 74,2649 h65
  text "SDA" at 1969.5,2636 h60
  text "GND" at 74,2549 h65
  text "V3.3" at 74,2449 h65
  text "RevA" at 787,2426 h55
  text "SCL" at 1970.5,2373 h60
  text "GNDRTN" at -1087.92,1806 h60
  text "Filter Life" at 1037,1686 h100
  text "1WIRE" at -1086,1571 h60
  text "Temperature" at 1036,1562 h100
  text "SLPZ" at -1086,1359 h60
  text "GPIO" at 1999,1307 h40
  text "SCL" at 1999,1207 h40
  text "maxim" at 609.07,1203.44 h238.71
  text "SDA" at 1999,1107 h40
  text "1W" at 1999,1007 h40
  text "integrated" at 609.07,971.62 h238.71
  text "Reset" at -953,950 h100
  text "GNDR" at 1999,907 h40
  text "V3.3" at 1999,806 h40
  text "DeepCover® Embedded Security in IoT" at -37,655 h110
  text "Authenticated Sensing & Notification" at -33,539 h100
  text "Provision" at -1018,484 h100
  text "MAXREFDES143#" at -37,300 h110
  text "1" at 1668,53 h40
  text "Invalidate" at -1019,29 h100
  text "RevA" at 1556,-84 h55
  text "Top Overlay" at 2742,-303 h53
Bottom Overlay:
  region: 227 vertices and 0 holes, not listed, extent 597.31,2585.65 865.64,2854.12
  text "1" at 81,2948 h40
  text "maxim" at 574.51,2746.8 h120
  text "integrated" at 574.51,2648.8 h120
  text "Bottom Overlay" at 5115.14,-905.69 h53
  text "Bottom Overlay" at 2743,-907 h53
Top Solder:
  text "Top Solder Mask" at 2743,-404 h53
Bottom Solder:
  text "Bottom Solder Mask" at 5115.14,-805.69 h53
  text "Bottom Solder Mask" at 2743,-807 h53
Mechanical 4:
  lines w0.5: 29.01,1532.17 29.01,1512.17 39,1512.17 48.99,1512.17 ; 28.99,1532.17 28.99,-8 1528.99,-8 1528.99,1492 68.99,1492 68.99,32 1488.99,32 1488.99,1452 108.99,1452 108.99,72 1448.99,72 1448.99,1412 148.99,1412 148.99,112 1408.99,112 1408.99,1372 188.99,1372 188.99,152 1368.99,152 1368.99,1332 228.99,1332 228.99,192 1328.99,192 1328.99,1292 268.99,1292 268.99,232 1288.99,232 1288.99,1252 308.99,1252 308.99,272 1248.99,272 1248.99,1212 348.99,1212 348.99,312 1208.99,312 1208.99,1172 388.99,1172 388.99,352 1168.99,352 1168.99,1132 428.99,1132 428.99,392 1128.99,392 1128.99,1092 468.99,1092 468.99,432 1088.99,432 1088.99,1052 508.99,1052 508.99,472 824.05,472 824.05,492 528.99,492 528.99,1032 1068.99,1032 1068.99,452 488.99,452 488.99,1072 1108.99,1072 1108.99,412 448.99,412 448.99,1112 1148.99,1112 1148.99,372 408.99,372 408.99,1152 1188.99,1152 1188.99,332 368.99,332 368.99,1192 1228.99,1192 1228.99,292 328.99,292 328.99,1232 1268.99,1232 1268.99,252 288.99,252 288.99,1272 1308.99,1272 1308.99,212 248.99,212 248.99,1312 1348.99,1312 1348.99,172 208.99,172 208.99,1352 1388.99,1352 1388.99,132 168.99,132 168.99,1392 1428.99,1392 1428.99,92 128.99,92 128.99,1432 1468.99,1432 1468.99,52 88.99,52 88.99,1472 1508.99,1472 1508.99,12 48.99,12 48.99,1512.17 ; 28.99,1532.17 29.01,1532.17 ; 29.01,1532.17 48.99,1532.17 ; 48.99,1512.17 708.99,1512.17 708.99,1522 708.99,1532.17 48.99,1532.17 ; 48.99,1512.17 48.99,1522 48.99,1532.17
  lines w1: -1298,-53.07 -1298,-127 -1224.07,-127 ; 2083.07,3373 2157,3373 2157,3299.07
Mechanical 10:
  lines w62: -102,2645 -102,2358 856.75,2358 ccw(c857.81,2461.19) 961,2460.13 961,2645 ; -102,2782 -102,3070 857.8,3070 cw(c857.24,2967.24) 960,2966.68 960,2782
Mechanical 11:
  text "Top Assembly" at -514.5,3765.5 h157.48
  text "TOP ASSEMBLY INFORMATION" at -386.5,-1129 h50
Mechanical 12:
  text "Bottom Assembly" at 1501,3519 h157.48
  text "BOTTOM ASSEMBLY INFORMATION" at -382.73,-1233 h50
  text "BOTTOM ASSEMBLY INFORMATION" at 929.5,-1317.5 h50
Mechanical 13:
  lines w0.5: 804,472 824,472 824,1531.97 804,1531.97 804,472
Mechanical 31:
  drawing of 103 lines, arcs and shapes, not listed
  text "MAXREFDES143#" at 2779,2231 h50
  text "Part Number: EPCBREFDES143" at 2779.5,2123.5 h50
  text "Property of" at 3176.5,2009.5 h50
  text "Rev" at 3943.5,1944.5 h50
  text "maxim" at 3173.02,1912.36 h120
  text "A" at 3992.5,1842.5 h50
  text "integrated" at 3173.02,1814.36 h120
  text "Notes:" at 5213,1804.5 h50
  text "Drill and Mechanical Layer" at 2781.5,1662.5 h50
  text "1." at 5213,1654.5 h50
  text "Material: RoHS Compliant FR-408 or similar laminate material" at 5413,1654.5 h50
  text "APR 24 2016" at 2788.5,1567 h50
  text "Units in mils" at 3526.5,1564.5 h50
  text "2." at 5213,1554.5 h50
  text "Board Dimensions: 3.455 x 3.500 mils" at 5413,1554.5 h50
  text "3." at 5213,1454.5 h50
  text "Board Thickness: 0.062 mils +/- 20%" at 5413,1454.5 h50
  text "SHAPE" at 2684,1379 h50
  text "SIZE" at 2984.5,1379 h50
  text "QTY" at 3251.5,1379 h50
  text "SYM" at 3429.5,1379 h50
  text "PLATED" at 3624.5,1379 h50
  text "TOLERANCE" at 3949.5,1379 h50
  text "4." at 5213,1354.5 h50
  text "Layers: 2 (Top, Bottom)" at 5413,1354.5 h50
  text "5." at 5213,1254.5 h50
  text "Minimum Trace Width / Trace Spacing: 10mil / 7mil" at 5413,1254.5 h50
  text "6." at 5213,1154.5 h50
  text "Copper Thickness: 1/2oz on all layers" at 5413,1154.5 h50
  text "ROUND" at 2686,1092.5 h50
  text "13" at 3028.5,1092 h50
  text "YES" at 3687.5,1092 h50
  text "+/- 0.001" at 3952.5,1091 h50
  text "47" at 3272,1087 h50
  text "7." at 5213,1054.5 h50
  text "Surface mount pads: 221" at 5413,1054.5 h50
  text "8." at 5213,954.5 h50
  text "Through holes: Quantity = 126,  minimum size = 0.013 mil" at 5413,954.5 h50
  text "28" at 3031.5,943 h50
  text "ROUND" at 2686,934.5 h50
  text "NO" at 3687.5,934 h50
  text "4" at 3294,933 h50
  text "+/- 0.003" at 3952.5,933 h50
  text "9." at 5213,854.5 h50
  text "Soldermask: BLUE" at 5413,854.5 h50
  text "28" at 3029.5,780 h50
  text "YES" at 3688,780 h50
  text "ROUND" at 2686,776.5 h50
  text "8" at 3299,775.5 h50
  text "+/- 0.003" at 3952.5,775 h50
  text "10." at 5213,754.5 h50
  text "Legend: White on Top and Bottom layers" at 5413,754.5 h50
  text "11." at 5213,654.5 h50
  text "Plating: HASL or similar" at 5413,654.5 h50
  text "ROUND" at 2686,618.5 h50
  text "52" at 3278,617 h50
  text "+/- 0.003" at 3952.5,617 h50
  text "39" at 3031,614 h50
  text "YES" at 3684.5,612 h50
  text "12." at 5213,554.5 h50
  text "Finish: Best finish option for lead free" at 5413,554.5 h50
  text "5" at 3302.89,462.36 h50
  text "ROUND" at 2686,460.5 h50
  text "+/- 0.003" at 3952.5,459 h50
  text "59" at 3031.5,458.5 h50
  text "YES" at 3684.5,454 h50
  text "13." at 5213,454.5 h50
  text "Vendor Logo & date code: Allowed on bottom side only" at 5413,454.5 h50
  text "14." at 5213,354.5 h50
  text "Testing Needed: Yes" at 5413,354.5 h50
  text "62" at 3034,303.5 h50
  text "ROUND" at 2686,302.5 h50
  text "4" at 3299,301.5 h50
  text "YES" at 3687.5,302 h50
  text "+/- 0.003" at 3952.5,301 h50
  text "15." at 5213,254.5 h50
  text "Tolerances:" at 5413,254.5 h50
  text "Plated-through holes +/- 0.003" at 5311.5,50.5 h50
  text "Metal to Metal +/- 0.001" at 5311.5,-49 h50
  text "Legend to legend +/- no preference" at 5311.5,-149 h50
  text "Soldermask to Metal +/- 0.002" at 5311.5,-249 h50
  text "PCB Core Material" at 2742,-603 h53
